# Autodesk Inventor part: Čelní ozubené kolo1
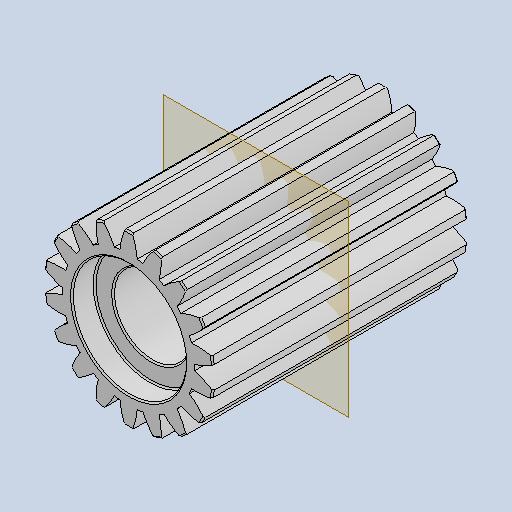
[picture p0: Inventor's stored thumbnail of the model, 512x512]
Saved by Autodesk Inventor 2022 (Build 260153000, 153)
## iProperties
CustomPartVersion: 1
Created: 2025-05
Part Number: Čelní ozubené kolo1
Material: Všeobecné
Document SubType Name: Modeling
Designer: jbart
Categories: <?xml version="1.0" encoding="UTF-16"?> <MemberInstance><Categories><FamilyTemplate><FamilyTemplateParameter ValueType="xs:double" Id="1" ObjectReferenceKey="da
Density: 1 g/cm^3
Appearance: Výchozí
Mass: 1135.55 g
Surface Area: 1687.53 cm^2
Volume: 1135.55 cm^3
Author: jbart
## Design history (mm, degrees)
sketch "Sketch1"
  geometry: C1 r 59.993 at (0, 0)
  constraints: 1 centre point
  dimensions: "d0" = 119.98507 diameter of C1 (= da_da)
extrude "Extrusion1" new body sketch "Sketch1" distance "d1" = 180 (= da_b); taper "d2" = 0 deg
workplane "Work Plane2"
sketch "Sketch2"
  geometry: C1 r 59.993 at (0, 0) reference; C2 r 54 at (0, 0)
  constraints: 1 centre point, 1 coincident
  dimensions: "d3" = 108 diameter of C2 (= da_d)
feature "Roztečný průměr" sketch "Sketch2" dims "d4" = 10, "d5" = 0
workplane "Work Plane8"
workplane "Work Plane9"
feature "Čelní ozubené kolo" dims "da_b" = 180, "da_d" = 108, "da_aw" = 189.61491, "da_da" = 119.98507, "da_df" = 93, "da_dw" = 108.35138, angle "da_beta" = 0 deg, "da_lefttooth" = 0, "da_righttooth" = 0
sketch "Náčrt3"
  geometry: C1 r 40 at (0, 0); 1 further point
  constraints: 1 centre point, 1 coincident
  dimensions: "d49" = 80 diameter of C1
extrude "Vysunutí2" cut sketch "Náčrt3" distance "d50" = 16; taper "d51" = 0 deg
node "Pracovní rovina11"
mirror "Zrcadlit1"
sketch "Náčrt4"
  geometry: C1 r 27 at (0, 0); 1 further point
  constraints: 1 centre point, 1 coincident
  dimensions: "d53" = 54 diameter of C1
extrude "Vysunutí3" cut sketch "Náčrt4" extent not by distance; stored distance "d54" = 0; taper "d55" = 0 deg
chamfer "Zkosení1" distance "d56" = 1; stored, may be unused: second distance "d57" = 2, angle "d58" = 45 deg
fillet "Zaoblení1" dims "d59" = 1
chamfer "Zkosení2" distance "d60" = 1; stored, may be unused: second distance "d61" = 2, angle "d62" = 45 deg
body "Solid1"
body "Srf1"
other parameters: "d16" = 189.61491 (= da_aw), "d17" = 0, "d34" = 10 deg (computed from da_z), "d39" = 0, "d41" = 0, "d43" = 189.61491 (= da_aw), "d46" = 189.61491 (= da_aw), "d47" = 0, "d48" = 0
